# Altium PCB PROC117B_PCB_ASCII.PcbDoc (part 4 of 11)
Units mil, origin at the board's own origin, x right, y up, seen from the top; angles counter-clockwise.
Board outline 2480.32 x 3185.25 mil, 8 copper layers (Top Layer, L2_GND1, L3_SIG1, L4_PWR1, L5_PWR2, L6_SIG2, L7_GND2, Bottom Layer), stack 57.4 mil thick; 456 components, 292 nets, 7831 pads, 2905 vias.
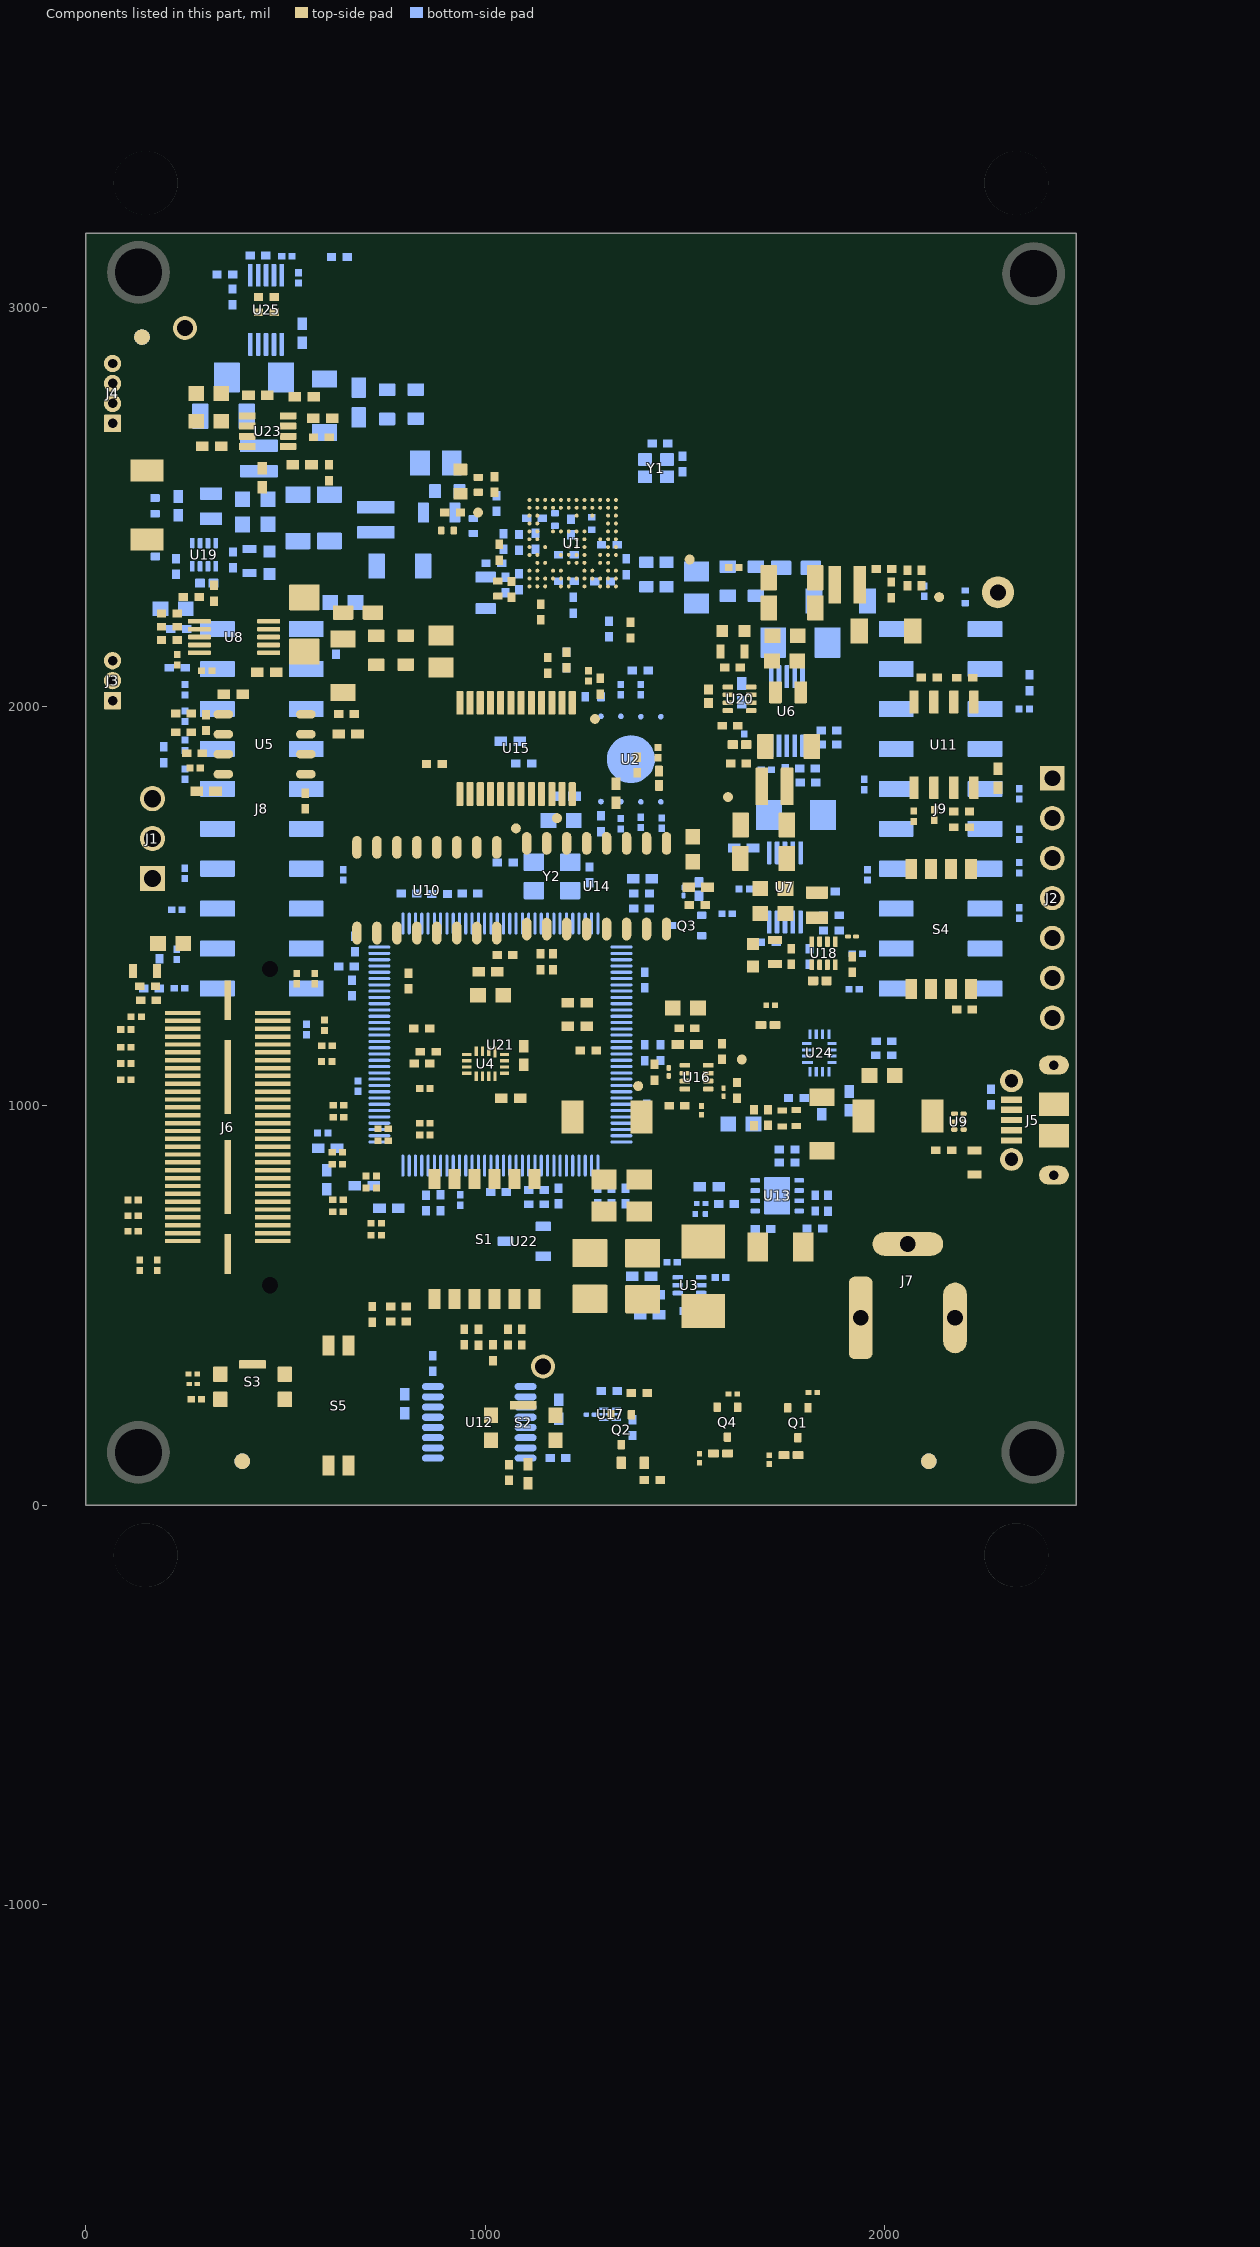
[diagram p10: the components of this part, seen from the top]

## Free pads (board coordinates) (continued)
  round 6 on Mech26: 1(175.86,1332.74) 1(175.86,1332.74) 1(175.86,1364.23) 1(175.86,1364.23) 1(179.87,1229.74) 1(179.87,1229.74) 1(179.87,1261.23) 1(179.87,1261.23) 1(188.87,1030.74) 1(188.87,1030.74) 1(188.87,1062.23) 1(188.87,1062.23) 1(190.87,1132.74) 1(190.87,1132.74) 1(190.87,1164.23) 1(190.87,1164.23) 1(196.39,1332.74) 1(196.39,1364.23) 1(200.4,1229.74) 1(200.4,1261.23) 1(209.39,1030.74) 1(209.39,1062.23) 1(211.39,1132.74) 1(211.39,1164.23) 1(214.39,1332.74) 1(214.39,1364.23) 1(218.4,1229.74) 1(218.4,1261.23) 1(220.93,-350.04) 1(221.93,-300.04) 1(223.93,-298.04) 1(223.93,-298.04) 1(223.93,-250.04) 1(223.93,-250.04) 1(227.39,1030.74) 1(227.39,1062.23) 1(229.39,1132.74) 1(229.39,1164.23) 1(234.91,1332.74) 1(234.91,1332.74) 1(234.91,1364.23) 1(234.91,1364.23) 1(234.93,-350.04) 1(234.93,-350.04) 1(234.93,-239.04) 1(238.93,1229.74) 1(238.93,1229.74) 1(238.93,1261.23) 1(238.93,1261.23) 1(247.92,1030.74) 1(247.92,1030.74) 1(247.92,1062.23) 1(247.92,1062.23) 1(249.92,1132.74) 1(249.92,1132.74) 1(249.92,1164.23) 1(249.92,1164.23) 1(249.93,-335.04) 1(300.65,530.96) 1(300.65,530.96) 1(300.65,551.49) 1(300.65,569.49) 1(300.65,590.02) 1(300.65,590.02) 1(303.93,508.96) 1(332.14,530.96) 1(332.14,530.96) 1(332.14,551.49) 1(332.14,569.49) 1(332.14,590.02) 1(332.14,590.02) 1(335.93,508.96) 1(335.93,508.96) 1(336.93,509.96) 1(405.02,362.56) 1(405.02,362.56) 1(405.02,383.09) 1(405.02,401.09) 1(405.02,421.62) 1(405.02,421.62) 1(405.02,432.56) 1(405.02,432.56) 1(405.02,453.09) 1(405.02,471.09) 1(405.02,491.62) 1(405.02,491.62) 1(436.51,362.56) 1(436.51,362.56) 1(436.51,383.09) 1(436.51,401.09) 1(436.51,421.62) 1(436.51,421.62) 1(436.51,432.56) 1(436.51,432.56) 1(436.51,453.09) 1(436.51,471.09) 1(436.51,491.62) 1(436.51,491.62) 1(529.77,2081.39) 1(529.77,2081.39) 1(529.77,2573.43) 1(529.77,2573.43) 1(537.21,2088.99) 1(537.21,2088.99) 1(537.21,2263.39) 1(537.21,2263.39) 1(537.29,2088.91) 1(537.29,2088.91) 1(537.29,2263.35) 1(537.29,2263.35) 1(576.13,2523.95) 1(576.13,2523.95) 1(578.01,2530.79) 1(578.01,2530.79) 1(578.13,2515.23) 1(578.13,2515.23) 1(578.17,2531.03) 1(578.17,2531.03) 1(578.25,2145.31) 1(578.25,2145.31) 1(578.25,2162.23) 1(578.25,2162.23) 1(580.37,2145.31) 1(580.37,2145.31) 1(580.37,2159.35) 1(580.37,2159.35) 1(580.45,2159.35) 1(580.45,2159.35) 1(581.33,2162.23) 1(581.33,2162.23) 1(581.61,2522.67) 1(581.61,2522.67) 1(582.49,2527.83) 1(582.49,2527.83) 1(582.57,2527.99) 1(582.57,2527.99) 1(583.09,2517.23) 1(583.09,2517.23) 1(583.81,2535.23) 1(583.81,2535.23) 1(585.73,2145.31) 1(585.73,2145.31) 1(586.69,2147.99) 1(586.69,2147.99) 1(587.01,2530.63) 1(587.01,2530.63) 1(587.61,2145.31) 1(587.61,2145.31) 1(587.77,2508.51) 1(587.77,2508.51) 1(590.09,2496.31) 1(590.09,2496.31) 1(592.01,2162.23) 1(592.01,2162.23) 1(592.65,2531.23) 1(592.65,2531.23) 1(592.69,2536.59) 1(592.69,2536.59) 1(592.93,2159.35) 1(592.93,2159.35) 1(592.97,2145.31) 1(592.97,2145.31) 1(592.97,2159.35) 1(592.97,2159.35) 1(595.09,2145.31) 1(595.09,2145.31) 1(595.09,2162.23) 1(595.09,2162.23) 1(595.13,2498.55) 1(595.13,2498.55) 1(596.97,2160.31) 1(596.97,2160.31) 1(596.97,2162.23) 1(596.97,2162.23) 1(602.65,2145.31) 1(602.65,2145.31) 1(602.65,2160.31) 1(602.65,2160.31) 1(602.65,2530.03) 1(602.65,2530.03) 1(602.77,2535.47) 1(602.77,2535.47) 1(604.85,2487.75) 1(604.85,2487.75) 1(604.89,2145.31) 1(604.89,2145.31) 1(604.89,2160.31) 1(604.89,2160.31) 1(610.53,2160.31) 1(610.53,2160.31) 1(610.53,2162.23) 1(610.53,2162.23) 1(610.61,2474.71) 1(610.61,2474.71) 1(611.17,2191.75) 1(611.17,2191.75) 1(611.17,2212.15) 1(611.17,2212.15) 1(611.93,2216.55) 1(611.93,2216.55) 1(613.21,2122.79) 1(613.21,2122.79) 1(613.21,2163.79) 1(613.21,2163.79) 1(614.05,2219.71) 1(614.05,2219.71) 1(614.65,2532.39) 1(614.65,2532.39) 1(614.77,2526.75) 1(614.77,2526.75) 1(616.69,2476.39) 1(616.69,2476.39) 1(617.33,2221.63) 1(617.33,2221.63) 1(617.73,2191.75) 1(617.73,2191.75) 1(617.73,2210.43) 1(617.73,2210.43) 1(619.25,2215.51) 1(619.25,2215.51) 1(620.33,2487.71) 1(620.33,2487.71) 1(620.81,2122.79) 1(620.81,2122.79) 1(620.81,2126.03) 1(620.81,2126.03) 1(620.93,2126.03) 1(620.93,2126.03) 1(621.13,2138.23) 1(621.13,2138.23) 1(621.13,2150.83) 1(621.13,2150.83) 1(621.13,2163.79) 1(621.13,2163.79) 1(621.22,-853.97) 1(621.25,2150.83) 1(621.25,2150.83) 1(621.33,2133.83) 1(621.33,2133.83) 1(621.33,2142.67) 1(621.33,2142.67) 1(621.73,2222.27) 1(621.73,2222.27) 1(621.93,2130.63) 1(621.93,2130.63) 1(621.93,2145.83) 1(621.93,2145.83) 1(623.21,2128.71) 1(623.21,2128.71) 1(623.21,2147.75) 1(623.21,2147.75) 1(623.53,2217.11) 1(623.53,2217.11) 1(623.93,2122.95) 1(623.93,2122.95) 1(624.09,2153.59) 1(624.09,2153.59) 1(625.37,2128.07) 1(625.37,2128.07) 1(625.37,2148.39) 1(625.37,2148.39) 1(626.53,2216.51) 1(626.53,2216.51) 1(626.73,2498.87) 1(626.73,2498.87) 1(627.01,2220.95) 1(627.01,2220.95) 1(627.45,2128.71) 1(627.45,2128.71) 1(627.45,2147.75) 1(627.45,2147.75) 1(627.93,2121.95) 1(627.93,2121.95) 1(627.93,2154.47) 1(627.93,2154.47) 1(627.97,2527.59) 1(627.97,2527.59) 1(628.61,2521.55) 1(628.61,2521.55) 1(628.73,2130.63) 1(628.73,2130.63) 1(628.73,2145.83) 1(628.73,2145.83) 1(628.77,2214.83) 1(628.77,2214.83) 1(629.33,2133.79) 1(629.33,2133.79) 1(629.33,2142.67) 1(629.33,2142.67) 1(629.49,2138.23) 1(629.49,2138.23) 1(630.21,2212.35) 1(630.21,2212.35) 1(630.39,-868.57) 1(630.39,-863.14) 1(630.39,-863.14) 1(630.61,2217.55) 1(630.61,2217.55) 1(630.73,2191.75) 1(630.73,2191.75) 1(630.73,2209.27) 1(630.73,2209.27) 1(630.73,2217.55) 1(630.73,2217.55) 1(630.73,2232.79) 1(630.73,2232.79) 1(632.17,2122.87) 1(632.17,2122.87) 1(632.17,2153.55) 1(632.17,2153.55) 1(634.89,2508.35) 1(634.89,2508.35) 1(635.13,2125.79) 1(635.13,2125.79) 1(635.13,2150.67) 1(635.13,2150.67) 1(636.85,2130.83) 1(636.85,2130.83) 1(636.85,2145.63) 1(636.85,2145.63) 1(636.93,2452.87) 1(636.93,2452.87) 1(637.29,2191.75) 1(637.29,2191.75) 1(637.29,2232.79) 1(637.29,2232.79) 1(637.41,2138.23) 1(637.41,2138.23) 1(641.93,2122.79) 1(641.93,2122.79) 1(642.29,2521.23) 1(642.29,2521.23) 1(642.53,2191.79) 1(642.53,2191.79) 1(642.53,2196.87) 1(642.53,2196.87) 1(642.53,2216.59) 1(642.53,2216.59) 1(642.53,2221.47) 1(642.53,2221.47) 1(642.69,2125.35) 1(642.69,2125.35) 1(642.89,2128.75) 1(642.89,2128.75) 1(642.89,2145.03) 1(642.89,2145.03) 1(643.29,2148.83) 1(643.29,2148.83) 1(643.73,2514.59) 1(643.73,2514.59) 1(644.97,2151.83) 1(644.97,2151.83) 1(645.29,2196.63) 1(645.29,2196.63) 1(646.77,2191.47) 1(646.77,2191.47) 1(647.97,2197.67) 1(647.97,2197.67) 1(648.37,2153.79) 1(648.37,2153.79) 1(648.45,2200.71) 1(648.45,2200.71) 1(648.45,2216.59) 1(648.45,2216.59) 1(648.45,2221.47) 1(648.45,2221.47) 1(648.45,2230.39) 1(648.45,2230.39) 1(649.49,2122.79) 1(649.49,2122.79) 1(650.49,2125.99) 1(650.49,2125.99) 1(650.49,2132.15) 1(650.49,2132.15) 1(650.49,2138.23) 1(650.49,2138.23) 1(650.49,2145.31) 1(650.49,2145.31) 1(650.57,2125.99) 1(650.57,2125.99) 1(650.93,2191.95) 1(650.93,2191.95) 1(651.17,2142.95) 1(651.17,2142.95) 1(651.33,2148.07) 1(651.33,2148.07) 1(652.13,2128.47) 1(652.13,2128.47) 1(653.41,2193.43) 1(653.41,2193.43) 1(653.57,2447.59) 1(653.57,2447.59) 1(653.61,2141.67) 1(653.61,2141.67) 1(653.77,2122.79) 1(653.77,2122.79) 1(653.85,2136.67) 1(653.85,2136.67) 1(654.09,2154.47) 1(654.09,2154.47) 1(654.13,2149.07) 1(654.13,2149.07) 1(654.61,2195.79) 1(654.61,2195.79) 1(654.97,2199.07) 1(654.97,2199.07) 1(654.97,2216.59) 1(654.97,2216.59) 1(654.97,2221.47) 1(654.97,2221.47) 1(654.97,2230.39) 1(654.97,2230.39) 1(655.37,2127.35) 1(655.37,2127.35) 1(656.89,2147.99) 1(656.89,2147.99) 1(656.89,2460.63) 1(656.89,2460.63) 1(657.17,2513.55) 1(657.17,2513.55) 1(657.33,2134.95) 1(657.33,2134.95) 1(657.65,2128.63) 1(657.65,2128.63) 1(657.81,2144.23) 1(657.81,2144.23) 1(657.81,2145.07) 1(657.81,2145.07) 1(658.13,2140.47) 1(658.13,2140.47) 1(658.33,2131.67) 1(658.33,2131.67) 1(658.33,2153.99) 1(658.33,2153.99) 1(658.45,2121.95) 1(658.45,2121.95) 1(659.93,2216.59) 1(659.93,2216.59) 1(659.93,2221.47) 1(659.93,2221.47) 1(661.65,2139.15) 1(661.65,2139.15) 1(661.77,2152.39) 1(661.77,2152.39) 1(661.97,2122.75) 1(661.97,2122.75) 1(664.05,2137.27) 1(664.05,2137.27) 1(664.09,2149.47) 1(664.09,2149.47) 1(664.25,2124.83) 1(664.25,2124.83) 1(664.25,2473.75) 1(664.25,2473.75) 1(664.57,2191.75) 1(664.57,2191.75) 1(664.57,2221.47) 1(664.57,2221.47) 1(664.57,2226.59) 1(664.57,2226.59) 1(664.57,2232.79) 1(664.57,2232.79) 1(664.93,2144.23) 1(664.93,2144.23) 1(664.93,2144.95) 1(664.93,2144.95) 1(665.49,2134.55) 1(665.49,2134.55) 1(665.53,2127.71) 1(665.53,2127.71) 1(665.93,517.2) 1(665.93,517.2) 1(665.93,525.96) 1(665.93,2130.83) 1(665.93,2130.83) 1(666.25,2433.27) 1(666.25,2433.27) 1(666.85,2151.51) 1(666.85,2151.51) 1(667.45,2156.03) 1(667.45,2156.03) 1(667.81,2145.99) 1(667.81,2145.99) 1(669.33,2159.95) 1(669.33,2159.95) 1(670.29,2430.91) 1(670.29,2430.91) 1(670.45,2142.15) 1(670.45,2142.15) 1(671.13,2191.75) 1(671.13,2191.75) 1(671.13,2221.47) 1(671.13,2221.47) 1(671.13,2226.59) 1(671.13,2226.59) 1(671.13,2232.79) 1(671.13,2232.79) 1(672.25,2504.79) 1(672.25,2504.79) 1(672.81,2162.75) 1(672.81,2162.75) 1(673.02,510.11) 1(673.17,2411.59) 1(673.17,2411.59) 1(673.97,2484.51) 1(673.97,2484.51) 1(674.57,2139.91) 1(674.57,2139.91) 1(675.13,2151.39) 1(675.13,2151.39) 1(676.05,2221.47) 1(676.05,2221.47) 1(676.13,2457.99) 1(676.13,2457.99) 1(676.45,2156.07) 1(676.45,2156.07) 1(676.65,2146.75) 1(676.65,2146.75) 1(677.29,2412.27) 1(677.29,2412.27) 1(678,1216.44) 1(678,1216.44) 1(678,1216.44) 1(678.13,2163.79) 1(678.13,2163.79) 1(679.89,2139.15) 1(679.89,2139.15) 1(680.65,2145.23) 1(680.65,2145.23) 1(680.89,2157.71) 1(680.89,2157.71) 1(681.93,2466.51) 1(681.93,2466.51) 1(682.69,2221.47) 1(682.69,2221.47) 1(683.69,2491.03) 1(683.69,2491.03) 1(684.33,2122.79) 1(684.33,2122.79) 1(684.33,2139.15) 1(684.33,2139.15) 1(684.33,2145.23) 1(684.33,2145.23) 1(684.33,2157.71) 1(684.33,2157.71) 1(684.37,2490.47) 1(684.37,2490.47) 1(685.33,2191.75) 1(685.33,2191.75) 1(686.33,2428.43) 1(686.33,2428.43) 1(686.5,1207.94) 1(686.5,1207.94) 1(686.5,1224.94) 1(686.5,1224.94) 1(687.05,2495.11) 1(687.05,2495.11) 1(688.57,2394.07) 1(688.57,2394.07) 1(688.73,2199.27) 1(688.73,2199.27) 1(688.85,2199.27) 1(688.85,2199.27) 1(689.02,-870.57) 1(689.02,-859.57) 1(689.02,-859.57) 1(689.03,-859.57) 1(691.93,2419.99) 1(691.93,2419.99) 1(692.05,2191.75) 1(692.05,2191.75) 1(692.61,2122.79) 1(692.61,2122.79) 1(692.61,2163.79) 1(692.61,2163.79) 1(693.85,2394.67) 1(693.85,2394.67) 1(694.21,2221.47) 1(694.21,2221.47) 1(697.57,2213.83) 1(697.57,2213.83) 1(697.69,2213.83) 1(697.69,2213.83) 1(699.81,2122.79) 1(699.81,2122.79) 1(699.81,2145.71) 1(699.81,2145.71) 1(700.33,2149.63) 1(700.33,2149.63) 1(700.81,2221.47) 1(700.81,2221.47) 1(701.25,2484.75) 1(701.25,2484.75) 1(701.89,2152.39) 1(701.89,2152.39) 1(703.17,2191.75) 1(703.17,2191.75) 1(704.37,2153.99) 1(704.37,2153.99) 1(704.93,2481.87) 1(704.93,2481.87) 1(706.05,2386.15) 1(706.05,2386.15) 1(706.37,2199.27) 1(706.37,2199.27) 1(706.49,2199.27) 1(706.49,2199.27) 1(707.69,2154.47) 1(707.69,2154.47) 1(707.73,2122.79) 1(707.73,2122.79) 1(707.73,2144.07) 1(707.73,2144.07) 1(707.81,2380.67) 1(707.81,2380.67) 1(707.97,2400.11) 1(707.97,2400.11) 1(708.53,2147.39) 1(708.53,2147.39) 1(708.77,2406.35) 1(708.77,2406.35) 1(709.21,2394.39) 1(709.21,2394.39) 1(710.05,2191.75) 1(710.05,2191.75) 1(711.13,2148.39) 1(711.13,2148.39) 1(711.81,2400.27) 1(711.81,2400.27) 1(711.85,2389.63) 1(711.85,2389.63) 1(712.13,2153.51) 1(712.13,2153.51) 1(712.29,2221.47) 1(712.29,2221.47) 1(712.33,2412.59) 1(712.33,2412.59) 1(712.37,2412.63) 1(712.37,2412.63) 1(712.45,2405.23) 1(712.45,2405.23) 1(712.57,2486.95) 1(712.57,2486.95) 1(712.81,2395.71) 1(712.81,2395.71) 1(713.29,2387.67) 1(713.29,2387.67) 1(713.33,2467.75) 1(713.33,2467.75) 1(714.25,2147.15) 1(714.25,2147.15) 1(714.89,2391.91) 1(714.89,2391.91) 1(715.21,2150.55) 1(715.21,2150.55) 1(715.29,2410.15) 1(715.29,2410.15) 1(715.33,2122.79) 1(715.33,2122.79) 1(715.33,2143.27) 1(715.33,2143.27) 1(715.33,2150.55) 1(715.33,2150.55) 1(715.33,2163.79) 1(715.33,2163.79) 1(715.41,2410.31) 1(715.41,2410.31) 1(715.57,2417.35) 1(715.57,2417.35) 1(716.37,2383.47) 1(716.37,2383.47) 1(716.37,2389.91) 1(716.37,2389.91) 1(719.25,2221.47) 1(719.25,2221.47) 1(720.25,2378.39) 1(720.25,2378.39) 1(721.65,2382.83) 1(721.65,2382.83) 1(722.61,2427.67) 1(722.61,2427.67) 1(723.09,2465.79) 1(723.09,2465.79) 1(723.25,2122.79) 1(723.25,2122.79) 1(723.25,2163.79) 1(723.25,2163.79) 1(723.97,2486.31) 1(723.97,2486.31) 1(724.85,2482.19) 1(724.85,2482.19) 1(725.81,2425.59) 1(725.81,2425.59) 1(726.25,2371.39) 1(726.25,2371.39) 1(727.21,2434.47) 1(727.21,2434.47) 1(727.93,2134.59) 1(727.93,2134.59) 1(727.93,2142.55) 1(727.93,2142.55) 1(728.45,2374.43) 1(728.45,2374.43) 1(728.57,2129.23) 1(728.57,2129.23) 1(728.61,2147.47) 1(728.61,2147.47) 1(730.33,2432.23) 1(730.33,2432.23) 1(730.65,2125.23) 1(730.65,2125.23) 1(730.73,2151.23) 1(730.73,2151.23) 1(731.01,2403.15) 1(731.01,2403.15) 1(734.13,2405.35) 1(734.13,2405.35) 1(734.17,2153.63) 1(734.17,2153.63) 1(734.17,2444.75) 1(734.17,2444.75) 1(734.29,2122.79) 1(734.29,2122.79) 1(735.13,2483.27) 1(735.13,2483.27) 1(735.49,2134.59) 1(735.49,2134.59) 1(735.49,2142.55) 1(735.49,2142.55) 1(736.17,2146.75) 1(736.17,2146.75) 1(736.41,2129.11) 1(736.41,2129.11) 1(737.41,2449.43) 1(737.41,2449.43) 1(737.45,2449.47) 1(737.45,2449.47) 1(738.57,2200.59) 1(738.57,2200.59) 1(738.97,2154.47) 1(738.97,2154.47) 1(739.05,2148.75) 1(739.05,2148.75) 1(739.33,2127.35) 1(739.33,2127.35) 1(739.41,2204.27) 1(739.41,2204.27) 1(739.57,2213.15) 1(739.57,2213.15) 1(739.69,2121.95) 1(739.69,2121.95) 1(739.81,2196.11) 1(739.81,2196.11) 1(740.77,2447.63) 1(740.77,2447.63) 1(740.97,2217.35) 1(740.97,2217.35) 1(741.41,2148.11) 1(741.41,2148.11) 1(741.53,2127.99) 1(741.53,2127.99) 1(741.61,2206.75) 1(741.61,2206.75) 1(741.93,2455.11) 1(741.93,2455.11) 1(742.81,2129.91) 1(742.81,2129.91) 1(742.81,2146.15) 1(742.81,2146.15) 1(742.89,2193.15) 1(742.89,2193.15) 1(743.45,2133.27) 1(743.45,2133.27) 1(743.45,2142.83) 1(743.45,2142.83) 1(743.61,2138.15) 1(743.61,2138.15) 1(743.77,2220.19) 1(743.77,2220.19) 1(744.05,2153.75) 1(744.05,2153.75) 1(744.33,2452.11) 1(744.33,2452.11) 1(744.65,2208.31) 1(744.65,2208.31) 1(744.89,2122.75) 1(744.89,2122.75) 1(745.13,2200.03) 1(745.13,2200.03) 1(745.73,2197.99) 1(745.73,2197.99) 1(745.93,2478.43) 1(745.93,2478.43) 1(746.05,2202.11) 1(746.05,2202.11) 1(746.37,2213.15) 1(746.37,2213.15) 1(746.45,2428.31) 1(746.45,2428.31) 1(746.69,2428.19) 1(746.69,2428.19) 1(747.21,2191.47) 1(747.21,2191.47) 1(747.29,2473.27) 1(747.29,2473.27) 1(747.41,2458.15) 1(747.41,2458.15) 1(747.45,2196.83) 1(747.45,2196.83) 1(747.57,2221.79) 1(747.57,2221.79) 1(747.89,2387.03) 1(747.89,2387.03) 1(747.97,2431.79) 1(747.97,2431.79) 1(748.01,2151.11) 1(748.01,2151.11) 1(748.17,2209.27) 1(748.17,2209.27) 1(748.17,2431.71) 1(748.17,2431.71) 1(748.25,2203.39) 1(748.25,2203.39) 1(748.53,2216.27) 1(748.53,2216.27) 1(748.57,2125.43) 1(748.57,2125.43) 1(748.69,2454.51) 1(748.69,2454.51) 1(749.65,2196.27) 1(749.65,2196.27) 1(750.61,2146.11) 1(750.61,2146.11) 1(750.81,2130.47) 1(750.81,2130.47) 1(751.33,2204.23) 1(751.33,2204.23) 1(751.53,2138.23) 1(751.53,2138.23) 1(751.73,2196.11) 1(751.73,2196.11) 1(751.73,2210.03) 1(751.73,2210.03) 1(751.85,2190.95) 1(751.85,2190.95) 1(751.97,2222.27) 1(751.97,2222.27) 1(752.41,2217.11) 1(752.41,2217.11) 1(752.49,2408.23) 1(752.49,2408.23) 1(753.21,2459.07) 1(753.21,2459.07) 1(753.33,2455.27) 1(753.33,2455.27) 1(754.81,2210.87) 1(754.81,2210.87) 1(754.85,2204.99) 1(754.85,2204.99) 1(755.53,2400.83) 1(755.53,2400.83) 1(755.85,2216.55) 1(755.85,2216.55) 1(756.09,2472.31) 1(756.09,2472.31) 1(756.17,2221.87) 1(756.17,2221.87) 1(756.21,2122.79) 1(756.21,2122.79) 1(756.21,2145.71) 1(756.21,2145.71) 1(756.29,2197.27) 1(756.29,2197.27) 1(756.33,2413.83) 1(756.33,2413.83) 1(756.73,2149.63) 1(756.73,2149.63) 1(757.01,2212.11) 1(757.01,2212.11) 1(757.05,2191.59) 1(757.05,2191.59) 1(757.61,2454.67) 1(757.61,2454.67) 1(757.81,2214.07) 1(757.81,2214.07) 1(758.29,2152.39) 1(758.29,2152.39) 1(758.37,2205.95) 1(758.37,2205.95) 1(758.45,2201.27) 1(758.45,2201.27) 1(758.45,2201.31) 1(758.45,2201.31) 1(758.53,2403.19) 1(758.53,2403.19) 1(758.61,2458.39) 1(758.61,2458.39) 1(759.13,2368.15) 1(759.13,2368.15) 1(759.69,2465.07) 1(759.69,2465.07) 1(759.97,2422.43) 1(759.97,2422.43) 1(760.01,2454.07) 1(760.01,2454.07) 1(760.21,2220.47) 1(760.21,2220.47) 1(760.73,2153.99) 1(760.73,2153.99) 1(760.97,2457.79) 1(760.97,2457.79) 1(761.21,2193.51) 1(761.21,2193.51) 1(761.41,2207.51) 1(761.41,2207.51) 1(761.57,2425.91) 1(761.57,2425.91) 1(762.09,2370.75) 1(762.09,2370.75) 1(763.21,2217.83) 1(763.21,2217.83) 1(763.57,2209.99) 1(763.57,2209.99) 1(763.97,2196.71) 1(763.97,2196.71) 1(764.05,2154.47) 1(764.05,2154.47) 1(764.13,2122.79) 1(764.13,2122.79) 1(764.13,2144.07) 1(764.13,2144.07) 1(764.37,2213.75) 1(764.37,2213.75) 1(764.93,2147.39) 1(764.93,2147.39) 1(765.05,2201.31) 1(765.05,2201.31) 1(765.45,2465.47) 1(765.45,2465.47) 1(766.01,2456.43) 1(766.01,2456.43) 1(767.13,2191.75) 1(767.13,2191.75) 1(767.53,2148.39) 1(767.53,2148.39) 1(768.25,2221.47) 1(768.25,2221.47) 1(768.53,2451.75) 1(768.53,2451.75) 1(768.61,2153.43) 1(768.61,2153.43) 1(770.61,2147.15) 1(770.61,2147.15) 1(771.73,2122.79) 1(771.73,2122.79) 1(771.73,2143.27) 1(771.73,2143.27) 1(771.93,2150.07) 1(771.93,2150.07) 1(772.05,2150.07) 1(772.05,2150.07) 1(772.05,2153.67) 1(772.05,2153.67) 1(772.05,2382.43) 1(772.05,2382.43) 1(772.13,2454.71) 1(772.13,2454.71) 1(773.77,2458.39) 1(773.77,2458.39) 1(774.77,2385.15) 1(774.77,2385.15) 1(775.01,2415.47) 1(775.01,2415.47) 1(775.13,2191.75) 1(775.13,2191.75) 1(775.25,2429.55) 1(775.25,2429.55) 1(775.93,2433.27) 1(775.93,2433.27) 1(776.29,2221.47) 1(776.29,2221.47) 1(776.77,2418.87) 1(776.77,2418.87) 1(777.05,2356.31) 1(777.05,2356.31) 1(778.85,2448.51) 1(778.85,2448.51) 1(779.61,2210.55) 1(779.61,2210.55) 1(779.65,2122.79) 1(779.65,2122.79) 1(779.65,2153.67) 1(779.65,2153.67) 1(780.81,2451.71) 1(780.81,2451.71) 1(784.21,2206.19) 1(784.21,2206.19) 1(785.45,2122.79) 1(785.45,2122.79) 1(785.45,2153.67) 1(785.45,2153.67) 1(788.13,2191.75) 1(788.13,2191.75) 1(788.13,2202.39) 1(788.13,2202.39) 1(788.13,2209.47) 1(788.13,2209.47) 1(788.13,2232.79) 1(788.13,2232.79) 1(789.05,2341.51) 1(789.05,2341.51) 1(790.97,2366.15) 1(790.97,2366.15) 1(791.49,2406.99) 1(791.49,2406.99) 1(793.01,2122.79) 1(793.01,2122.79) 1(793.01,2126.39) 1(793.01,2126.39) 1(793.01,2343.47) 1(793.01,2343.47) 1(793.13,2126.39) 1(793.13,2126.39) 1(793.21,2424.39) 1(793.21,2424.39) 1(793.37,2133.15) 1(793.37,2133.15) 1(793.37,2153.67) 1(793.37,2153.67) 1(793.37,2369.15) 1(793.37,2369.15) 1(793.41,2410.31) 1(793.41,2410.31) 1(794.37,2428.03) 1(794.37,2428.03) 1(794.45,2129.31) 1(794.45,2129.31) 1(794.65,2232.79) 1(794.65,2232.79) 1(794.69,2191.75) 1(794.69,2191.75) 1(794.69,2232.79) 1(794.69,2232.79) 1(796.45,2123.03) 1(796.45,2123.03) 1(797.57,2128.07) 1(797.57,2128.07) 1(798.25,2215.79) 1(798.25,2215.79) 1(798.25,2222.11) 1(798.25,2222.11) 1(800.04,1216.44) 1(800.17,2129.07) 1(800.17,2129.07) 1(800.69,2222.27) 1(800.69,2222.27) 1(800.97,2132.35) 1(800.97,2132.35) 1(800.97,2153.67) 1(800.97,2153.67) 1(801.01,2121.95) 1(801.01,2121.95) 1(801.05,2216.07) 1(801.05,2216.07) 1(803.69,2221.71) 1(803.69,2221.71) 1(804.21,2215.39) 1(804.21,2215.39) 1(804.33,2122.47) 1(804.33,2122.47) 1(806.29,2220.19) 1(806.29,2220.19) 1(806.77,2213.43) 1(806.77,2213.43) 1(806.81,2124.07) 1(806.81,2124.07) 1(807.01,2329.51) 1(807.01,2329.51) 1(808.29,2218.07) 1(808.29,2218.07) 1(808.37,2126.83) 1(808.37,2126.83) 1(808.49,2210.27) 1(808.49,2210.27) 1(808.89,2130.75) 1(808.89,2130.75) 1(808.89,2153.67) 1(808.89,2153.67) 1(809.09,2191.75) 1(809.09,2191.75) 1(809.09,2205.91) 1(809.09,2205.91) 1(809.13,2396.71) 1(809.13,2396.71) 1(809.41,2215.71) 1(809.41,2215.71) 1(809.49,2215.71) 1(809.49,2215.71) 1(809.49,2221.47) 1(809.49,2221.47) 1(810.29,2332.07) 1(810.29,2332.07) 1(811.21,2399.91) 1(811.21,2399.91) 1(812.97,2415.39) 1(812.97,2415.39) 1(813.13,2351.35) 1(813.13,2351.35) 1(814.13,2122.79) 1(814.13,2122.79) 1(814.53,2418.87) 1(814.53,2418.87) 1(814.93,2125.35) 1(814.93,2125.35) 1(815.09,2128.75) 1(815.09,2128.75) 1(815.09,2145.03) 1(815.09,2145.03) 1(815.17,2354.59) 1(815.17,2354.59) 1(815.53,2148.83) 1(815.53,2148.83) 1(815.65,2191.75) 1(815.65,2191.75) 1(815.65,2221.47) 1(815.65,2221.47) 1(817.17,2151.83) 1(817.17,2151.83) 1(820.61,2153.79) 1(820.61,2153.79) 1(821.73,2122.79) 1(821.73,2122.79) 1(821.73,2206.63) 1(821.73,2206.63) 1(822.69,2125.99) 1(822.69,2125.99) 1(822.69,2132.15) 1(822.69,2132.15) 1(822.69,2138.23) 1(822.69,2138.23) 1(822.69,2145.31) 1(822.69,2145.31) 1(822.73,2200.35) 1(822.73,2200.35) 1(822.73,2212.91) 1(822.73,2212.91) 1(822.81,2125.99) 1(822.81,2125.99) 1(823.41,2142.95) 1(823.41,2142.95) 1(823.53,2148.07) 1(823.53,2148.07) 1(824.33,2128.47) 1(824.33,2128.47) 1(825.65,2195.35) 1(825.65,2195.35) 1(825.65,2217.87) 1(825.65,2217.87) 1(825.85,2141.67) 1(825.85,2141.67) 1(826.01,2122.79) 1(826.01,2122.79) 1(826.09,2136.67) 1(826.09,2136.67) 1(826.33,2154.47) 1(826.33,2154.47) 1(826.37,2149.07) 1(826.37,2149.07) 1(827.01,2318.63) 1(827.01,2318.63) 1(827.57,2127.35) 1(827.57,2127.35) 1(827.61,2384.31) 1(827.61,2384.31) 1(828.25,2206.63) 1(828.25,2206.63) 1(828.73,2202.83) 1(828.73,2202.83) 1(828.73,2210.43) 1(828.73,2210.43) 1(829.13,2147.99) 1(829.13,2147.99) 1(829.21,2321.79) 1(829.21,2321.79) 1(829.53,2134.95) 1(829.53,2134.95) 1(829.89,2128.63) 1(829.89,2128.63) 1(829.89,2387.39) 1(829.89,2387.39) 1(830.05,2144.23) 1(830.05,2144.23) 1(830.05,2145.07) 1(830.05,2145.07) 1(830.29,2199.43) 1(830.29,2199.43) 1(830.29,2213.79) 1(830.29,2213.79) 1(830.33,2140.47) 1(830.33,2140.47) 1(830.33,2192.11) 1(830.33,2192.11) 1(830.33,2221.11) 1(830.33,2221.11) 1(830.53,2153.99) 1(830.53,2153.99) 1(830.57,2131.67) 1(830.57,2131.67) 1(830.69,2121.95) 1(830.69,2121.95) 1(832.89,2197.03) 1(832.89,2197.03) 1(832.89,2216.19) 1(832.89,2216.19) 1(833.81,2402.99) 1(833.81,2402.99) 1(833.85,2139.15) 1(833.85,2139.15) 1(834.01,2152.39) 1(834.01,2152.39) 1(834.21,2122.75) 1(834.21,2122.75) 1(835.81,2406.23) 1(835.81,2406.23) 1(836.29,2137.27) 1(836.29,2137.27) 1(836.33,2149.47) 1(836.33,2149.47) 1(836.49,2124.83) 1(836.49,2124.83) 1(836.69,2190.95) 1(836.69,2190.95) 1(836.69,2196.11) 1(836.69,2196.11) 1(836.69,2217.11) 1(836.69,2217.11) 1(836.69,2222.27) 1(836.69,2222.27) 1(837.17,2144.23) 1(837.17,2144.23) 1(837.17,2144.95) 1(837.17,2144.95) 1(837.69,2134.55) 1(837.69,2134.55) 1(837.77,2127.71) 1(837.77,2127.71) 1(838.17,2130.83) 1(838.17,2130.83) 1(839.25,2337.43) 1(839.25,2337.43) 1(840.49,2197.03) 1(840.49,2197.03) 1(840.49,2216.19) 1(840.49,2216.19) 1(840.93,2340.87) 1(840.93,2340.87) 1(841.09,2122.79) 1(841.09,2122.79) 1(841.09,2129.55) 1(841.09,2129.55) 1(843.05,2192.11) 1(843.05,2192.11) 1(843.05,2221.11) 1(843.05,2221.11) 1(843.13,2199.43) 1(843.13,2199.43) 1(843.13,2213.79) 1(843.13,2213.79) 1(844.65,2202.83) 1(844.65,2202.83) 1(844.65,2210.43) 1(844.65,2210.43) 1(845.17,2206.63) 1(845.17,2206.63) 1(846.65,2369.47) 1(846.65,2369.47) 1(847.77,2195.35) 1(847.77,2195.35) 1(847.77,2217.87) 1(847.77,2217.87) 1(849.13,2372.39) 1(849.13,2372.39) 1(849.45,2308.67) 1(849.45,2308.67) 1(850.09,2312.55) 1(850.09,2312.55) 1(850.69,2200.35) 1(850.69,2200.35) 1(850.69,2212.91) 1(850.69,2212.91) 1(851.69,2206.63) 1(851.69,2206.63) 1(853.73,2232.79) 1(853.73,2232.79) 1(855.05,2387.47) 1(855.05,2387.47) 1(855.73,2129.55) 1(855.73,2129.55) 1(855.73,2163.79) 1(855.73,2163.79) 1(857.45,2390.47) 1(857.45,2390.47) 1(861.01,2232.79) 1(861.01,2232.79) 1(864.01,2122.79) 1(864.01,2122.79) 1(864.01,2163.79) 1(864.01,2163.79) 1(865.05,2191.75) 1(865.05,2191.75) 1(865.37,2322.27) 1(865.37,2322.27) 1(865.89,2351.91) 1(865.89,2351.91) 1(868.05,2324.91) 1(868.05,2324.91) 1(868.57,2354.63) 1(868.57,2354.63) 1(868.65,2201.39) 1(868.65,2201.39) 1(868.77,2201.39) 1(868.77,2201.39) 1(870.77,2312.15) 1(870.77,2312.15) 1(872.17,2318.11) 1(872.17,2318.11) 1(872.33,2191.75) 1(872.33,2191.75) 1(873.17,2304.03) 1(873.17,2304.03) 1(874.65,2299.51) 1(874.65,2299.51) 1(875.73,2309.83) 1(875.73,2309.83) 1(876.81,2232.79) 1(876.81,2232.79) 1(876.85,2368.47) 1(876.85,2368.47) 1(877.17,2301.31) 1(877.17,2301.31) 1(877.21,2298.67) 1(877.21,2298.67) 1(880.33,2370.39) 1(880.33,2370.39) 1(880.57,2223.11) 1(880.57,2223.11) 1(880.69,2223.11) 1(880.69,2223.11) 1(882.81,2317.19) 1(882.81,2317.19) 1(884.17,2232.79) 1(884.17,2232.79) 1(885.01,2122.79) 1(885.01,2122.79) 1(885.01,2163.79) 1(885.01,2163.79) 1(885.09,2331.27) 1(885.09,2331.27) 1(887.81,2310.99) 1(887.81,2310.99) 1(888.01,2333.75) 1(888.01,2333.75) 1(889.05,2191.75) 1(889.05,2191.75) 1(892.45,2201.39) 1(892.45,2201.39) 1(892.57,2201.39) 1(892.57,2201.39) 1(893.29,2122.79) 1(893.29,2122.79) 1(893.29,2163.79) 1(893.29,2163.79) 1(896.49,2191.75) 1(896.49,2191.75) 1(896.69,2347.67) 1(896.69,2347.67) 1(897.77,2157.03) 1(897.77,2157.03) 1(897.77,2163.79) 1(897.77,2163.79) 1(899.01,2310.99) 1(899.01,2310.99) 1(899.97,2232.79) 1(899.97,2232.79) 1(901.09,2348.43) 1(901.09,2348.43) 1(904.13,2305.35) 1(904.13,2305.35) 1(906.73,2122.79) 1(906.73,2122.79) 1(906.73,2157.03) 1(906.73,2157.03) 1(907.29,2232.79) 1(907.29,2232.79) 1(914.13,2325.67) 1(914.13,2325.67) 1(914.93,2306.27) 1(914.93,2306.27) 1(915.01,2122.79) 1(915.01,2122.79) 1(915.01,2157.03) 1(915.01,2157.03) 1(919.17,2325.15) 1(919.17,2325.15) 1(919.45,2301.15) 1(919.45,2301.15) 1(923.97,2157.03) 1(923.97,2157.03) 1(923.97,2163.79) 1(923.97,2163.79) 1(925.37,1679.43) 1(925.37,1679.43) 1(928.81,2302.87) 1(928.81,2302.87) 1(932.17,1566.96) 1(932.17,1686.23) 1(932.17,1686.23) 1(932.17,2298.27) 1(932.17,2298.27) 1(932.3,1686.23) 1(934.21,2301.07) 1(934.21,2301.07) 1(936.21,2297.43) 1(936.21,2297.43) 1(939.1,1679.43) 1(939.1,1679.43) 1(977.97,2088.99) 1(977.97,2088.99) 1(977.97,2263.39) 1(977.97,2263.39) 1(978.09,2088.91) 1(978.09,2088.91) 1(978.09,2263.35) 1(978.09,2263.35) 1(985.57,2081.39) 1(985.57,2081.39) 1(985.57,2573.43) 1(985.57,2573.43) 1(1022.02,1371.96) 1(1022.02,1371.96) 1(1029.56,1364.43) 1(1030.39,1364.43) 1(1030.39,1364.43) 1(1030.39,1514.43) 1(1037.93,1371.96) 1(1037.93,1371.96) 1(1048.4,-1695.57) 1(1048.4,-1695.57) 1(1048.4,-1195.57) 1(1048.4,-1195.57) 1(1136.39,1231.96) 1(1172.05,1231.96) 1(1172.05,1231.96) 1(1184.02,1168.43) 1(1192.58,1211.43) 1(1193.47,1158.98) 1(1193.47,1158.98) 1(1208.02,1158.98) 1(1217.71,-875.34) 1(1217.71,-848.25) 1(1217.71,-848.25) 1(1224.93,-841.04) 1(1281.93,-927.04) 1(1281.93,-912.04) 1(1281.93,-912.04) 1(1292.93,-901.04) 1(1292.93,-901.04) 1(1292.93,-855.04) 1(1292.93,-855.04) 1(1314.93,-833.04) 1(1444.93,802.96) 1(1457.93,802.96) 1(1457.93,802.96) 1(1472.93,1131.96) 1(1483.93,828.96) 1(1483.93,1131.96) 1(1529.93,786.81) 1(1537.79,794.68) 1(1537.79,794.68) 1(1574.65,794.68) 1(1574.65,794.68) 1(1577.02,1032.43) 1(1586.99,1022.46) 1(1586.99,1022.46) 1(1588.34,808.37) 1(1588.34,808.37) 1(1597.43,1022.46) 1(1597.43,1022.46) 1(1601.34,808.37) 1(1601.34,808.37) 1(1602.93,952.96) 1(1612.93,952.96) 1(1612.93,952.96) 1(1613.93,1005.96) 1(1613.93,1005.96) 1(1618.93,825.96) 1(1618.93,825.96) 1(1618.93,850.96) 1(1625.16,488.48) 1(1634.93,984.96) 1(1640.93,924.96) 1(1659.16,488.48) 1(1695.76,310.48) 1(1695.76,310.48) 1(1695.76,341.97) 1(1695.76,341.97) 1(1695.76,345.48) 1(1695.76,345.48) 1(1695.76,376.97) 1(1695.76,376.97) 1(1708.93,1189.96) 1(1711.82,180.96) 1(1711.82,194.93) 1(1715.93,1182.96) 1(1715.93,1182.96) 1(1716.28,310.48) 1(1716.28,341.97) 1(1716.28,345.48) 1(1716.28,376.97) 1(1734.28,310.48) 1(1734.28,341.97) 1(1734.28,345.48) 1(1734.28,376.97) 1(1754.81,310.48) 1(1754.81,310.48) 1(1754.81,341.97) 1(1754.81,341.97) 1(1754.81,345.48) 1(1754.81,345.48) 1(1754.81,376.97) 1(1754.81,376.97) 1(1754.93,1182.96) 1(1879.93,1566.96) 1(1886.93,1573.96) 1(1886.93,1573.96) 1(1892.93,1573.96) 1(1915.65,1246.95) 1(1915.65,1246.95) 1(1915.65,1267.48) 1(1915.65,1285.48) 1(1915.65,1306) 1(1915.65,1306) 1(1947.14,1246.95) 1(1947.14,1246.95) 1(1947.14,1267.48) 1(1947.14,1285.48) 1(1947.14,1306) 1(1947.14,1306) 1(1948.4,-1695.57) 1(1948.4,-1695.57) 1(1948.4,-1195.57) 1(1948.4,-1195.57) 1(1995.93,245.96) 1(1995.93,425.96) 1(1995.93,425.96) 1(2013.93,443.96) 1(2013.93,443.96) 1(2015.94,225.95) 1(2054.93,2721.96) 1(2056.93,486.96) 1(2056.93,495.96) 1(2059.82,182.83) 1(2064.93,187.96) 1(2064.93,187.96) 1(2066.93,2721.96) 1(2066.93,2721.96) 1(2074.93,2713.96) 1(2103.52,187.96) 1(2104.93,514.96) 1(2125.93,514.96) 1(2125.93,514.96) 1(2137.93,502.96) 1(2186.93,443.96) 1(2186.93,443.96) 1(2189.91,225.95) 1(2189.91,225.95) 1(2189.93,-581.04) 1(2189.93,-581.04) 1(2189.93,-375.04) 1(2189.93,-375.04) 1(2195.53,465.36) 1(2204.93,-596.04) 1(2204.93,-596.04) 1(2205.93,241.96) 1(2205.93,241.96) 1(2205.93,424.96) 1(2205.93,424.96) 1(2207.93,-357.04) 1(2207.93,-357.04) 1(2263.53,465.36) 1(2319.04,-316.04) 1(2330.93,909.96) 1(2330.93,909.96) 1(2330.93,939.96) 1(2354.43,886.46) 1(2371.49,871.68) 1(2371.49,871.68) 1(2371.49,903.18) 1(2371.49,903.18) 1(2382.82,-316.04) 1(2392.02,871.68) 1(2392.02,903.18) 1(2407.93,-357.04) 1(2407.93,-357.04) 1(2410.02,871.68) 1(2410.02,903.18) 1(2413.93,-596.04) 1(2413.93,-596.04) 1(2425.93,-584.04) 1(2425.93,-584.04) 1(2425.93,-375.04) 1(2425.93,-375.04) 1(2430.54,871.68) 1(2430.54,871.68) 1(2430.54,903.18) 1(2430.54,903.18)
  round 3.9 on Mech26: 1(189.86,-1447.05) 1(189.86,-1385.99) 1(189.86,-1249.3) 1(189.86,-1188.24) 1(189.86,-1049.44) 1(189.86,-988.38) 1(250.93,-1447.05) 1(250.93,-1385.99) 1(250.93,-1249.3) 1(250.93,-1188.24) 1(250.93,-1049.44) 1(250.93,-988.38) 1(332.12,391.72) 1(332.12,414.2) 1(332.12,449.98) 1(332.12,472.46) 1(340.04,391.72) 1(340.04,414.2) 1(340.04,449.98) 1(340.04,472.46) 1(346.49,-1169.1) 1(346.49,-1108.04) 1(351.81,391.72) 1(351.81,414.2) 1(351.81,449.98) 1(351.81,472.46) 1(359.72,391.72) 1(359.72,414.2) 1(359.72,449.98) 1(359.72,472.46) 1(371.49,391.72) 1(371.49,414.2) 1(371.49,449.98) 1(371.49,472.46) 1(379.41,391.72) 1(379.41,414.2) 1(379.41,449.98) 1(379.41,472.46) 1(407.56,-1169.1) 1(407.56,-1108.04) 1(496.49,-1391.1) 1(496.49,-1330.04) 1(557.56,-1391.1) 1(557.56,-1330.04) 1(839.12,1058.49) 1(839.12,1086.09) 1(839.12,1158.88) 1(839.12,1186.48) 1(856.88,1058.49) 1(856.88,1086.09) 1(856.88,1158.88) 1(856.88,1186.48) 1(876.52,1058.49) 1(876.52,1086.09) 1(876.52,1158.88) 1(876.52,1186.48) 1(887.12,-440.1) 1(887.12,-379.04) 1(894.28,1058.49) 1(894.28,1086.09) 1(894.28,1158.88) 1(894.28,1186.48) 1(913.93,1058.49) 1(913.93,1086.09) 1(913.93,1158.88) 1(913.93,1186.48) 1(931.68,1058.49) 1(931.68,1086.09) 1(931.68,1158.88) 1(931.68,1186.48) 1(948.19,-440.1) 1(948.19,-379.04) 1(1156.49,-1174.1) 1(1156.49,-1113.04) 1(1217.56,-1174.1) 1(1217.56,-1113.04) 1(1839.53,323.48) 1(1839.53,345.57) 1(1880.86,-857.05) 1(1880.86,-795.99) 1(1923.82,323.48) 1(1923.82,345.57) 1(1941.93,-857.05) 1(1941.93,-795.99) 1(1985.86,-1102.05) 1(1985.86,-1040.99) 1(2046.93,-1102.05) 1(2046.93,-1040.99)
  round 15.75 on Mech26: 1(375.45,419.29)
  round 157.48 on Mech26: 1(391.39,2183.48) 1(391.39,2931.51) 1(391.39,3250.19) 1(2320.53,2183.48) 1(2320.53,2931.51) 1(2320.53,3250.19)
  round 23.98 on Mech26: 1(475.92,883.94)
  round 19.68 on Mech26: 1(512.74,435.86) 1(680.28,609.72) 1(687.28,759.77) 1(764.02,283.83) 1(768.02,464.83) 1(993.4,251.08) 1(1382.43,263.35) 1(2237.53,199.92)
  round 51 on Mech26: 1(610.52,2281.37) 1(610.52,3009.37) 1(1902.03,2281.37) 1(1902.03,3009.37)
